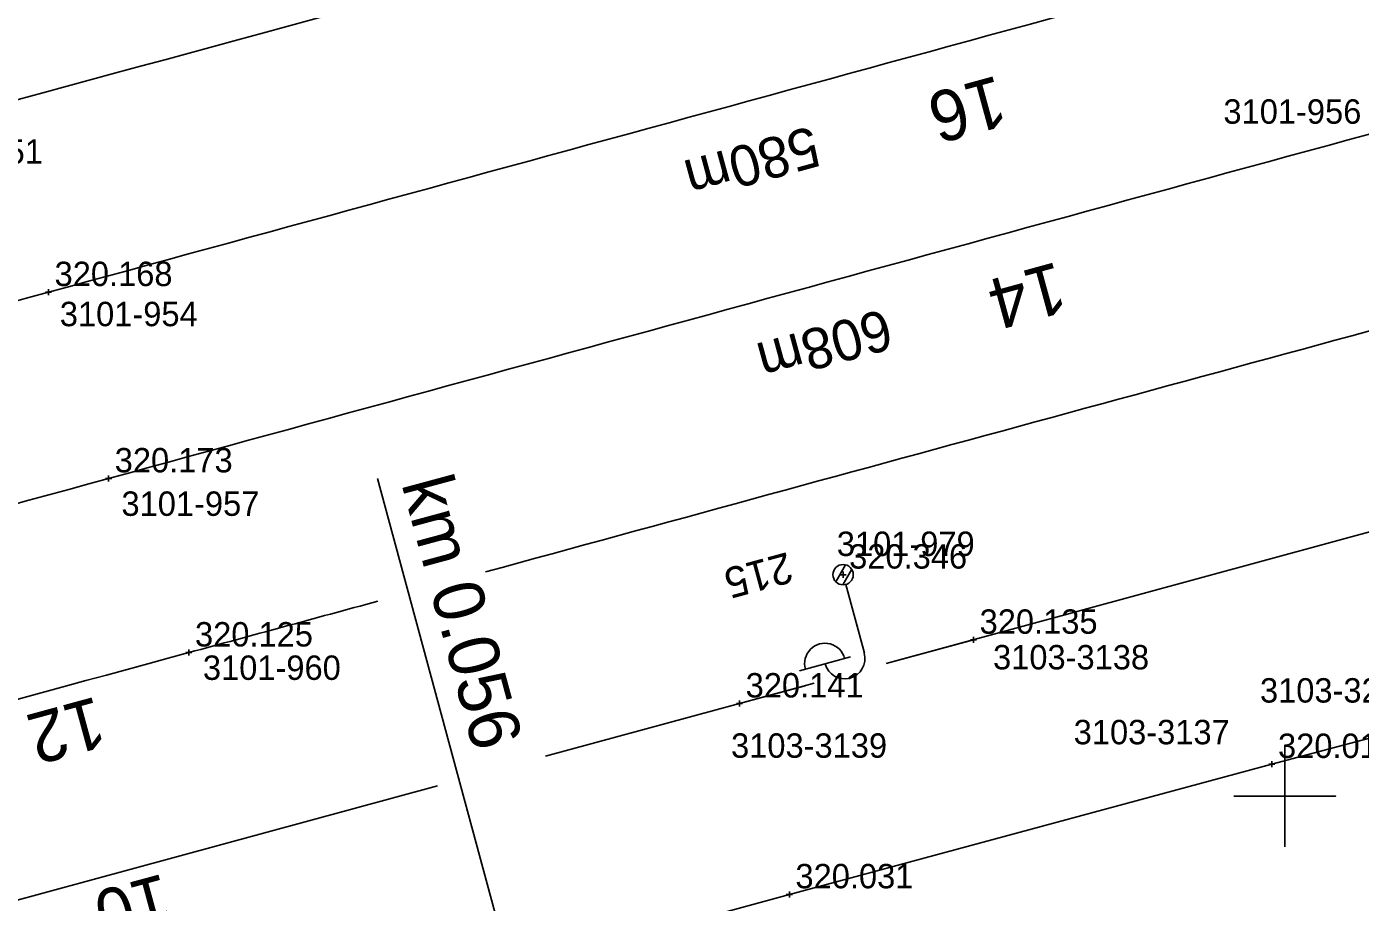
# Model space of a CAD drawing. Extents: x -821875 to -821475, y -1070280 to -1069975.
# Drawn here: x -821680.94 to -821648.14, y -1070202.61 to -1070181.08 of the extents above; entities that cross this region are included whole.
import ezdxf

# ---------------------------------------------------------------- set-up
doc = ezdxf.new("R2010")
doc.units = 0
for name, color, linetype in [('Vrstva 1', 7, 'Continuous'), ('Vrstva 25', 7, 'Continuous'), ('Vrstva 3', 7, 'Continuous'), ('Vrstva 4', 7, 'Continuous'), ('Vrstva 6', 7, 'Continuous'), ('Vrstva 60', 7, 'Continuous'), ('Vrstva 61', 7, 'Continuous')]:
    doc.layers.add(name, color=color, linetype=linetype)

# ---------------------------------------------------------------- blocks, each defined once
blk = doc.blocks.new('BOD')
at = {"layer": 'Vrstva 3'}
for p, q in [((-0.15, 0), (0.15, 0)), ((0, -0.15), (0, 0.15))]:
    blk.add_line(p, q, dxfattribs=at)

msp = doc.modelspace()

# ---------------------------------------------------------------- linework, layer by layer
at = {"layer": 'Vrstva 1'}
for p, q in [((-821635.257, -1070190.05), (-821659.741, -1070196.727)), ((-821661.572, -1070197.227), (-821663.407, -1070197.727))]:
    msp.add_line(p, q, dxfattribs=at)
for points in [[(-821663.407, -1070197.727), (-821668.175, -1070199.024)], [(-821646.625, -1070198.235), (-821650.317, -1070199.215), (-821662.183, -1070202.42), (-821668.007, -1070204.011)], [(-821651.25, -1070200), (-821650, -1070200), (-821650, -1070198.75), (-821650, -1070200), (-821648.75, -1070200), (-821650, -1070200), (-821650, -1070201.25)], [(-821670.833, -1070199.746), (-821688.982, -1070204.681)]]:
    msp.add_lwpolyline(points, dxfattribs=at)
for points in [[(-821500, -1070134.157), (-821525.227, -1070140.424), (-821545.665, -1070145.962), (-821584.89, -1070156.649), (-821608.863, -1070163.173), (-821645.742, -1070173.228), (-821684.141, -1070183.689)], [(-821500, -1070139.002), (-821505.719, -1070140.359), (-821526.796, -1070145.75), (-821547.362, -1070151.333), (-821583.687, -1070161.245), (-821611.332, -1070168.765), (-821648.899, -1070179.006), (-821680.4, -1070187.609), (-821711.133, -1070195.974)], [(-821500, -1070143.947), (-821500.602, -1070144.082), (-821526.98, -1070150.62), (-821544.477, -1070155.432), (-821558.026, -1070159.151), (-821579.135, -1070164.951), (-821610.376, -1070173.463), (-821647.463, -1070183.595), (-821678.921, -1070192.191), (-821710.276, -1070200.761)], [(-821500, -1070148.817), (-821511.77, -1070151.622), (-821530.609, -1070156.564), (-821556.604, -1070163.701), (-821576.895, -1070169.217), (-821607.294, -1070177.525), (-821643.435, -1070187.343), (-821669.656, -1070194.488)], [(-821679.285, -1070162.663), (-821695.528, -1070167.095), (-821716.799, -1070174.043), (-821730.799, -1070179.932), (-821744.379, -1070186.736), (-821755.356, -1070192.851), (-821764.427, -1070198.469)], [(-821677.113, -1070166.912), (-821699.427, -1070173.07), (-821715.575, -1070178.704), (-821729.749, -1070184.723), (-821746.361, -1070192.156), (-821759.601, -1070198.262)], [(-821672.303, -1070195.209), (-821676.947, -1070196.473), (-821709.336, -1070205.287)]]:
    msp.add_spline(points, degree=3, dxfattribs=at)
at = {"layer": 'Vrstva 25'}
for p, q in [((-821660.803, -1070194.315), (-821661.042, -1070194.73)), ((-821660.65, -1070194.424), (-821660.87, -1070194.806)), ((-821660.796, -1070194.799), (-821660.339, -1070196.488)), ((-821660.677, -1070196.579), (-821661.933, -1070196.919))]:
    msp.add_line(p, q, dxfattribs=at)
msp.add_circle((-821660.862, -1070194.557), 0.25, dxfattribs=at)
msp.add_circle((-821660.862, -1070194.557), 0.25, dxfattribs=at)
for centre, start, end in [((-821661.307, -1070196.743), 14.438, 195.8431), ((-821660.822, -1070196.618), 195.1405, 15.1405)]:
    msp.add_arc(centre, 0.5, start, end, dxfattribs=at)
at = {"layer": 'Vrstva 4'}
for points in [[(-821657.655, -1070196.16), (-821659.803, -1070196.745)], [(-821661.791, -1070197.287), (-821663.407, -1070197.727)], [(-821650.317, -1070199.215), (-821662.183, -1070202.42)]]:
    msp.add_lwpolyline(points, dxfattribs=at)
at = {"layer": 'Vrstva 6'}
msp.add_line((-821669.424, -1070202.853), (-821672.307, -1070192.193), dxfattribs=at)

# ---------------------------------------------------------------- block references
at = {"layer": 'Vrstva 60', "xscale": 0.5, "yscale": 0.5}
for p in [(-821680.4, -1070187.609), (-821678.921, -1070192.191), (-821660.862, -1070194.557), (-821657.655, -1070196.16), (-821676.947, -1070196.473), (-821663.407, -1070197.727), (-821650.317, -1070199.215), (-821662.183, -1070202.42)]:
    msp.add_blockref('BOD', p, dxfattribs=at)

# ---------------------------------------------------------------- texts
at = {"layer": 'Vrstva 1'}
for s, height, rotation, p in [('16', 1.25, 195.2814, (-821657.065, -1070182.272)), ('580m', 1, 195.2858, (-821661.612, -1070183.515)), ('14', 1.25, 195.2829, (-821655.596, -1070186.854)), ('608m', 1, 195.283, (-821659.827, -1070188.01)), ('12', 1.25, 195.2356, (-821679.217, -1070197.544)), ('10', 1.25, 195.1889, (-821677.573, -1070201.9))]:
    msp.add_text(s, height=height, rotation=rotation, dxfattribs=at).set_placement(p)
at = {"layer": 'Vrstva 25'}
msp.add_text('215', height=0.75, rotation=195.1406, dxfattribs=at).set_placement((-821662.227, -1070193.996))
at = {"layer": 'Vrstva 6'}
msp.add_text('km 0.056', height=1.25, rotation=285.133, dxfattribs=at).set_placement((-821671.726, -1070192.315))
at = {"layer": 'Vrstva 60'}
for s, p in [('3101-956', (-821651.509, -1070183.466)), ('3101-951', (-821683.929, -1070184.45)), ('3101-954', (-821680.121, -1070188.446)), ('3101-957', (-821678.605, -1070193.11)), ('3101-979', (-821661.016, -1070194.097)), ('3103-3138', (-821657.174, -1070196.886)), ('3101-960', (-821676.603, -1070197.144)), ('3103-3233', (-821650.611, -1070197.702)), ('3103-3137', (-821655.191, -1070198.728)), ('3103-3139', (-821663.616, -1070199.059))]:
    msp.add_text(s, height=0.6, dxfattribs=at).set_placement(p)
at = {"layer": 'Vrstva 61'}
for s, p in [('320.168', (-821680.25, -1070187.459)), ('320.173', (-821678.771, -1070192.041)), ('320.346', (-821660.712, -1070194.407)), ('320.135', (-821657.505, -1070196.01)), ('320.125', (-821676.797, -1070196.323)), ('320.141', (-821663.257, -1070197.577)), ('320.012', (-821650.167, -1070199.065)), ('320.031', (-821662.033, -1070202.27))]:
    msp.add_text(s, height=0.6, dxfattribs=at).set_placement(p)

doc.saveas('drawing.dxf')
